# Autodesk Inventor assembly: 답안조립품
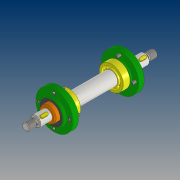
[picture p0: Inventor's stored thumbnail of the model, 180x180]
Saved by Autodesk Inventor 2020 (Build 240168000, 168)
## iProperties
Created: 2021-08
Part Number: 답안조립품
Document SubType Name: Assembly
Designer: PC312-
Author: PC312-
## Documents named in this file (9)
- C:\Users\PC312-\Desktop\710809V1003\답안조립품.iam
- C:\Users\PC312-\Desktop\710809V1003\본체.ipt
- C:\Users\PC312-\Desktop\710809V1003\커버.ipt
- C:\Users\PC312-\Desktop\710809V1003\베어링 6203.ipt
- C:\Users\PC312-\Desktop\710809V1003\축.ipt
- C:\Users\PC312-\Desktop\710809V1003\키 5x5x12.ipt
- C:\Users\PC312-\Desktop\710809V1003\부시.ipt
- C:\Users\PC312-\Desktop\710809V1003\오일 실 26 38 8.ipt
- C:\Users\PC312-\Desktop\710809V1003\볼트 M4.ipt
